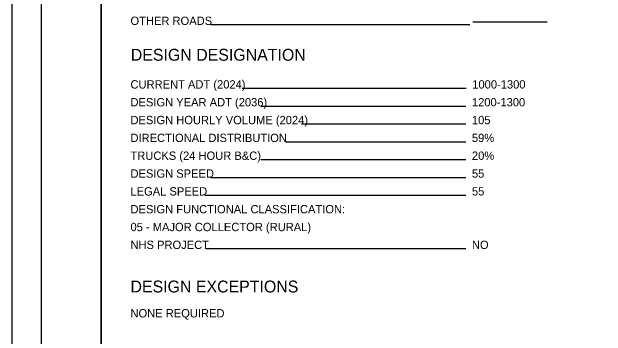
# Model space of a CAD drawing. Extents: x 0 to 34, y 0 to 22.
# Drawn here: x 0 to 9.99, y 5.64 to 11.1 of the extents above; entities that cross this region are included whole.
import ezdxf

# ---------------------------------------------------------------- set-up
doc = ezdxf.new("R2010")
doc.units = 0
for name, color, linetype in [('SH_Border', 7, 'Continuous'), ('SH_Cut_Line', 7, 'Continuous'), ('SH_Data', 7, 'Continuous'), ('SH_Text', 7, 'Continuous')]:
    doc.layers.add(name, color=color, linetype=linetype)

msp = doc.modelspace()

# ---------------------------------------------------------------- linework, layer by layer
at = {"layer": 'SH_Border'}
for points in [[(0.5, 21.5), (1.5, 21.5), (1.5, 0.5), (0.5, 0.5)], [(1.5, 21.5), (33.5, 21.5), (33.5, 0.5), (1.5, 0.5)]]:
    msp.add_lwpolyline(points, close=True, dxfattribs=at)
at = {"layer": 'SH_Cut_Line'}
msp.add_lwpolyline([(0, 0), (34, 0), (34, 22), (0, 22)], close=True, dxfattribs=at)
at = {"layer": 'SH_Data'}
for p, q in [((9, 10.9223), (7.75, 10.9223)), ((7.7, 10.8767), (3.3471, 10.8767)), ((7.6424, 9.8062), (3.871, 9.8062)), ((7.6368, 9.5062), (4.1885, 9.5062)), ((7.6368, 9.2062), (4.8723, 9.2062)), ((7.6368, 8.9062), (4.6037, 8.9062)), ((7.6368, 8.6062), (4.1885, 8.6062)), ((7.6368, 8.3062), (3.346, 8.3062)), ((7.6368, 8.0062), (3.2422, 8.0062)), ((7.6368, 7.1062), (3.2669, 7.1062))]:
    msp.add_line(p, q, dxfattribs=at)

# ---------------------------------------------------------------- texts
msp.add_text('DESIGN DESIGNATION', height=0.2, dxfattribs=at).set_placement((2, 10.2747))
at = {"layer": 'SH_Text'}
for s, height, p in [('OTHER ROADS', 0.14, (1.9944, 10.8767)), ('CURRENT ADT (2024)', 0.14, (1.9944, 9.8062)), ('1000-1300', 0.14, (7.7424, 9.8062)), ('DESIGN YEAR ADT (2036)', 0.14, (1.9944, 9.5062)), ('1200-1300', 0.14, (7.7368, 9.5062)), ('DESIGN HOURLY VOLUME (2024)', 0.14, (1.9944, 9.2062)), ('105', 0.14, (7.7368, 9.2062)), ('DIRECTIONAL DISTRIBUTION', 0.14, (1.9944, 8.9062)), ('59%', 0.14, (7.7368, 8.9062)), ('TRUCKS (24 HOUR B&C)', 0.14, (1.9944, 8.6062)), ('20%', 0.14, (7.7368, 8.6062)), ('DESIGN SPEED', 0.14, (1.9944, 8.3062)), ('55', 0.14, (7.7368, 8.3062)), ('LEGAL SPEED', 0.14, (1.9944, 8.0062)), ('55', 0.14, (7.7368, 8.0062)), ('DESIGN FUNCTIONAL CLASSIFICATION:', 0.14, (1.9944, 7.7062)), ('05 - MAJOR COLLECTOR (RURAL)', 0.14, (1.9944, 7.4062)), ('NHS PROJECT', 0.14, (1.9944, 7.1062)), ('NO', 0.14, (7.7368, 7.1062)), ('DESIGN EXCEPTIONS', 0.2, (1.9944, 6.3744)), ('NONE REQUIRED', 0.14, (1.9944, 5.9544))]:
    msp.add_text(s, height=height, dxfattribs=at).set_placement(p)

doc.saveas('drawing.dxf')
